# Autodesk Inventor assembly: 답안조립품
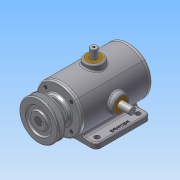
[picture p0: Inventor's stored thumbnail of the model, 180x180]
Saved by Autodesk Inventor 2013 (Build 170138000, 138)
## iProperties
Created: 2014-11
Part Number: 답안조립품
Document SubType Name: Assembly
Designer: Administrator
Mass: 3490.54 g
Surface Area: 2329.55 cm^2
Volume: 1071.41 cm^3
Density: 3.2579 g/cm^3
Author: Administrator
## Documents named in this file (15)
- C:\Users\Administrator\Desktop\341123V1018\답안조립품.iam
- C:\Users\Administrator\Desktop\341123V1018\KS B 1028  - 납작점M4x5.ipt
- C:\Users\Administrator\Desktop\341123V1018\KS B 1311 - 5 x 5 x 18I.ipt
- C:\Users\Administrator\Desktop\341123V1018\M4-소켓머리.ipt
- C:\Users\Administrator\Desktop\341123V1018\V-벨트풀리.ipt
- C:\Users\Administrator\Desktop\341123V1018\뒷커버.ipt
- C:\Users\Administrator\Desktop\341123V1018\베어링 6203.ipt
- C:\Users\Administrator\Desktop\341123V1018\본체.ipt
- C:\Users\Administrator\Desktop\341123V1018\부시.ipt
- C:\Users\Administrator\Desktop\341123V1018\슬라이더.ipt
- C:\Users\Administrator\Desktop\341123V1018\앞커버.ipt
- C:\Users\Administrator\Desktop\341123V1018\오일실.ipt
- C:\Users\Administrator\Desktop\341123V1018\축.ipt
- C:\Users\Administrator\Desktop\341123V1018\스프링1.ipt
- C:\Users\Administrator\Desktop\341123V1018\스프링2.ipt
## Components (14 placed, 6 different names)
1. KS B 1028 납작점 - 미터 납작점M4x5:1 — 플러쉬:6
2. KS B 1311 (I) 5 x 5 x 18:1
3. V-벨트풀리:1 — 플러쉬:1
4. 7-베어링 6203:1
5. 8-오일실:1 — 플러쉬:2
6. 7-베어링 6203:2
7. 9-M4-소켓머리:1
8. 9-M4-소켓머리:3
9. 9-M4-소켓머리:4
10. 9-M4-소켓머리:5
11. 9-M4-소켓머리:2
12. 9-M4-소켓머리:6
13. 9-M4-소켓머리:7
14. 9-M4-소켓머리:8
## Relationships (3: Flush 3)
- 플러쉬:1 [Flush]: V-벨트풀리:1
- 플러쉬:2 [Flush]: 8-오일실:1
- 플러쉬:6 [Flush]: KS B 1028 납작점 - 미터 납작점M4x5:1
